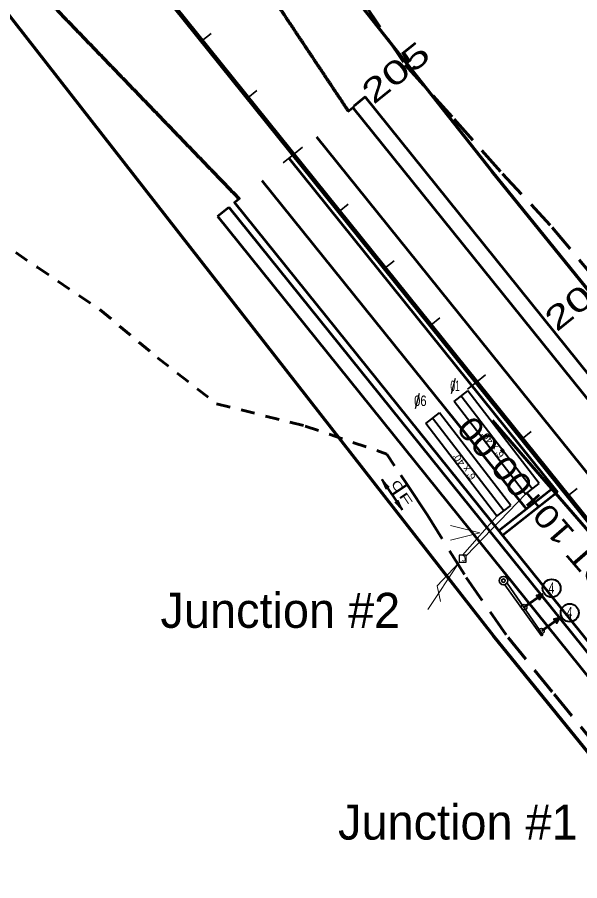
# Model space of a CAD drawing. Extents: x 2717836 to 2719883, y 337327 to 339813.
# Drawn here: x 2718118.9 to 2718311.5, y 339092.2 to 339388.1 of the extents above; entities that cross this region are included whole.
import ezdxf
from ezdxf.enums import TextEntityAlignment as Align

# ---------------------------------------------------------------- set-up
doc = ezdxf.new("R2010")
doc.units = 0
doc.header["$LTSCALE"] = 3.2
for name, pattern in [('LONG_DASHED', [7.5, 6, -1.5]), ('MEDIUM_DASHED', [4.5, 3, -1.5]), ('SHORT_DASHED', [2.7, 1.5, -1.2])]:
    doc.linetypes.add(name, pattern=pattern)
for name, color, linetype, lineweight in [('1', 7, 'Continuous', 106), ('17', 7, 'Continuous', 40), ('18', 7, 'Continuous', 35), ('2', 7, 'Continuous', 13), ('22', 7, 'SHORT_DASHED', 60), ('23', 7, 'Continuous', 70), ('28', 7, 'Continuous', 25), ('3', 7, 'Continuous', 70), ('31', 7, 'Continuous', 35), ('4', 7, 'Continuous', 53), ('50', 7, 'Continuous', 13), ('52', 7, 'Continuous', 53), ('7', 7, 'Continuous', 53)]:
    doc.layers.add(name, color=color, linetype=linetype, lineweight=lineweight)

msp = doc.modelspace()

# ---------------------------------------------------------------- hatches: boundary and pattern name
at = {"layer": '52'}
for points in [[(2718243.745, 339229.709), (2718246.246, 339227.048), (2718245.241, 339227.459), (2718245.221, 339226.365)], [(2718250.677, 339219.307), (2718248.176, 339221.969), (2718249.182, 339221.558), (2718249.201, 339222.652)]]:
    msp.add_hatch(color=256, dxfattribs=at).paths.add_polyline_path(points)

# ---------------------------------------------------------------- linework, layer by layer
at = {"layer": '1'}
msp.add_line((2717900.042, 339730.601), (2718401.027, 339107.905), dxfattribs=at)
at = {"layer": '1', "lineweight": 13}
msp.add_lwpolyline([(2718267.269, 339213.9), (2718277.269, 339211.4), (2718267.269, 339208.9)], dxfattribs=at)
at = {"layer": '17'}
for p, q in [((2718268.483, 339256.414), (2718273.236, 339260.076)), ((2718295.271, 339226.558), (2718270.859, 339258.245)), ((2718297.648, 339228.389), (2718273.236, 339260.076)), ((2718292.895, 339224.727), (2718268.483, 339256.414)), ((2718258.76, 339248.883), (2718263.513, 339252.545)), ((2718287.925, 339220.858), (2718263.513, 339252.545)), ((2718283.172, 339217.196), (2718258.76, 339248.883)), ((2718285.548, 339219.027), (2718261.136, 339250.714)), ((2718292.895, 339224.727), (2718297.648, 339228.389)), ((2718283.172, 339217.196), (2718287.925, 339220.858))]:
    msp.add_line(p, q, dxfattribs=at)
at = {"layer": '17', "lineweight": 25}
msp.add_lwpolyline([(2718270.265, 339203.803), (2718270.265, 339201.403), (2718272.665, 339201.403), (2718272.665, 339203.803)], close=True, dxfattribs=at)
at = {"layer": '18'}
for p, q in [((2718286.407, 339197.797), (2718286.44, 339197.796)), ((2718298.438, 339176.096), (2718285.836, 339193.638))]:
    msp.add_line(p, q, dxfattribs=at)
at = {"layer": '18', "lineweight": 60}
for p, q in [((2718298.846, 339190.415), (2718292.565, 339186.048)), ((2718304.717, 339182.352), (2718298.514, 339177.874))]:
    msp.add_line(p, q, dxfattribs=at)
at = {"layer": '18'}
msp.add_lwpolyline([(2718286.613, 339194.252), (2718298.867, 339176.528), (2718298.438, 339176.096)], dxfattribs=at)
at = {"layer": '18', "lineweight": 40}
for points in [[(2718298.846, 339190.415), (2718296.75, 339190.002), (2718297.729, 339188.594)], [(2718304.717, 339182.352), (2718302.629, 339181.902), (2718303.632, 339180.512)]]:
    msp.add_lwpolyline(points, close=True, dxfattribs=at)
at = {"layer": '18'}
for radius in [1.448, 0.621]:
    msp.add_circle((2718285.395, 339195.059), radius, dxfattribs=at)
at = {"layer": '18', "lineweight": 40}
for centre in [(2718301.9, 339192.442), (2718308.096, 339184.054)]:
    msp.add_circle(centre, 3.09, dxfattribs=at)
at = {"layer": '18', "lineweight": 25}
for centre in [(2718292.485, 339185.989), (2718298.435, 339177.814)]:
    msp.add_circle(centre, 0.96, dxfattribs=at)
at = {"layer": '2', "lineweight": 53}
for p, q in [((2718302.51, 339226.85), (2718283.843, 339212.08)), ((2718303.918, 339225.414), (2718285.097, 339210.521))]:
    msp.add_line(p, q, dxfattribs=at)
at = {"layer": '2'}
msp.add_lwpolyline([(2718259.544, 339185.135), (2718270.069, 339201.126), (2718262.662, 339193.326), (2718263.832, 339187.865)], dxfattribs=at)
at = {"layer": '22', "linetype": 'MEDIUM_DASHED'}
for p, q in [((2718237.804, 339392.698), (2718251.724, 339371.81)), ((2718251.724, 339371.81), (2718268.485, 339353.209)), ((2718268.485, 339353.209), (2718285.099, 339334.488)), ((2718285.099, 339334.488), (2718302.106, 339316.085)), ((2718302.106, 339316.085), (2718318.127, 339296.888)), ((2718259.373, 339217.531), (2718272.661, 339196.135)), ((2718272.661, 339196.135), (2718286.987, 339175.575)), ((2718286.987, 339175.575), (2718302.767, 339156.183)), ((2718302.767, 339156.183), (2718318.581, 339136.82))]:
    msp.add_line(p, q, dxfattribs=at)
at = {"layer": '22'}
for p, q in [((2718104.052, 339317.175), (2718125.672, 339302.483)), ((2718125.672, 339302.483), (2718147.311, 339287.806)), ((2718147.311, 339287.806), (2718166.862, 339271.448)), ((2718166.862, 339271.448), (2718187.132, 339255.67)), ((2718187.132, 339255.67), (2718217.512, 339248.025)), ((2718217.512, 339248.025), (2718245.459, 339238.423)), ((2718245.459, 339238.423), (2718252.416, 339227.977))]:
    msp.add_line(p, q, dxfattribs=at)
at = {"layer": '22', "linetype": 'LONG_DASHED'}
msp.add_line((2718252.416, 339227.977), (2718259.373, 339217.531), dxfattribs=at)
at = {"layer": '23'}
for p, q in [((2718281.942, 339176.113), (2718019.958, 339512.184)), ((2718281.562, 339335.271), (2718222.313, 339410.323))]:
    msp.add_line(p, q, dxfattribs=at)
for points in [[(2718450.804, 339126.177), (2718423.202, 339160.278), (2718356.64, 339242.515), (2718281.562, 339335.271)], [(2718625.836, 338603.023), (2718449.262, 338959.135), (2718424.429, 339000.578), (2718281.942, 339176.113)]]:
    msp.add_lwpolyline(points, dxfattribs=at)
at = {"layer": '28'}
for p, q in [((2718267.641, 339259.176), (2718269.003, 339264.412)), ((2718255.249, 339254.07), (2718256.612, 339259.306))]:
    msp.add_line(p, q, dxfattribs=at)
at = {"layer": '3'}
for points in [[(2718125.07, 339398.259), (2718125.544, 339397.767), (2718126.011, 339397.283), (2718126.485, 339396.792), (2718126.952, 339396.308), (2718127.426, 339395.816), (2718127.893, 339395.332), (2718128.367, 339394.84), (2718128.841, 339394.349), (2718129.308, 339393.865), (2718129.782, 339393.373), (2718130.249, 339392.889), (2718130.723, 339392.398), (2718131.19, 339391.914), (2718131.664, 339391.422), (2718132.137, 339390.93), (2718132.605, 339390.446), (2718133.078, 339389.955), (2718133.546, 339389.471), (2718134.019, 339388.979), (2718134.487, 339388.495), (2718134.96, 339388.003), (2718135.428, 339387.52), (2718135.901, 339387.028), (2718136.375, 339386.536), (2718136.842, 339386.052), (2718137.316, 339385.561), (2718137.783, 339385.077), (2718138.257, 339384.585), (2718138.724, 339384.101), (2718139.198, 339383.609), (2718139.672, 339383.118), (2718140.139, 339382.634), (2718140.613, 339382.142), (2718141.08, 339381.658), (2718141.554, 339381.166), (2718142.021, 339380.683), (2718142.495, 339380.191), (2718142.968, 339379.699), (2718143.436, 339379.215), (2718143.909, 339378.724), (2718144.377, 339378.24), (2718144.85, 339377.748), (2718145.318, 339377.264), (2718145.791, 339376.772), (2718146.265, 339376.281), (2718146.732, 339375.797), (2718147.206, 339375.305), (2718147.673, 339374.821), (2718148.147, 339374.329), (2718148.614, 339373.846), (2718149.088, 339373.354), (2718149.562, 339372.862), (2718150.029, 339372.378), (2718150.503, 339371.887), (2718150.97, 339371.403), (2718151.444, 339370.911), (2718151.911, 339370.427), (2718152.385, 339369.935), (2718152.852, 339369.451), (2718153.326, 339368.96), (2718153.799, 339368.468), (2718154.267, 339367.984), (2718154.74, 339367.492), (2718155.208, 339367.009), (2718155.681, 339366.517), (2718156.149, 339366.033), (2718156.622, 339365.541), (2718157.096, 339365.05), (2718157.563, 339364.566), (2718158.037, 339364.074), (2718158.504, 339363.59), (2718158.978, 339363.098), (2718159.445, 339362.614), (2718159.919, 339362.123)], [(2718204.33, 339397.853), (2718204.709, 339397.285), (2718205.081, 339396.725), (2718205.46, 339396.157), (2718205.833, 339395.597), (2718206.212, 339395.029), (2718206.584, 339394.469), (2718206.963, 339393.901), (2718207.342, 339393.333), (2718207.715, 339392.773), (2718208.094, 339392.205), (2718208.466, 339391.645), (2718208.845, 339391.077), (2718209.218, 339390.517), (2718209.597, 339389.949), (2718209.975, 339389.381), (2718210.348, 339388.821), (2718210.727, 339388.253), (2718211.1, 339387.693), (2718211.478, 339387.125), (2718211.851, 339386.565), (2718212.23, 339385.997), (2718212.603, 339385.437), (2718212.981, 339384.869), (2718213.36, 339384.301), (2718213.733, 339383.741), (2718214.112, 339383.173), (2718214.484, 339382.612), (2718214.863, 339382.044), (2718215.236, 339381.484), (2718215.615, 339380.916), (2718215.994, 339380.348), (2718216.366, 339379.788), (2718216.745, 339379.22), (2718217.118, 339378.66), (2718217.497, 339378.092), (2718217.869, 339377.532), (2718218.248, 339376.964), (2718218.627, 339376.396), (2718219, 339375.836), (2718219.378, 339375.268), (2718219.751, 339374.708), (2718220.13, 339374.14), (2718220.503, 339373.58), (2718220.881, 339373.012), (2718221.26, 339372.444), (2718221.633, 339371.884), (2718222.012, 339371.316), (2718222.384, 339370.756), (2718222.763, 339370.188), (2718223.136, 339369.628), (2718223.515, 339369.06), (2718223.894, 339368.492), (2718224.266, 339367.932), (2718224.645, 339367.364), (2718225.018, 339366.804), (2718225.397, 339366.236), (2718225.769, 339365.676), (2718226.148, 339365.108), (2718226.521, 339364.548), (2718226.9, 339363.98), (2718227.278, 339363.412), (2718227.651, 339362.852), (2718228.03, 339362.284), (2718228.403, 339361.724), (2718228.781, 339361.156), (2718229.154, 339360.595), (2718229.533, 339360.028), (2718229.912, 339359.46), (2718230.284, 339358.899), (2718230.663, 339358.331), (2718231.036, 339357.771), (2718231.415, 339357.203), (2718232.166, 339356.075)], [(2718159.919, 339362.123), (2718160.393, 339361.631), (2718160.86, 339361.147), (2718161.334, 339360.655), (2718161.801, 339360.172), (2718162.275, 339359.68), (2718162.742, 339359.196), (2718163.216, 339358.704), (2718163.689, 339358.213), (2718164.157, 339357.729), (2718164.63, 339357.237), (2718165.098, 339356.753), (2718165.571, 339356.261), (2718166.039, 339355.777), (2718166.512, 339355.286), (2718166.986, 339354.794), (2718167.453, 339354.31), (2718167.927, 339353.818), (2718168.394, 339353.335), (2718168.868, 339352.843), (2718169.335, 339352.359), (2718169.809, 339351.867), (2718170.276, 339351.383), (2718170.75, 339350.892), (2718171.224, 339350.4), (2718171.691, 339349.916), (2718172.165, 339349.424), (2718172.632, 339348.94), (2718173.106, 339348.449), (2718173.573, 339347.965), (2718174.047, 339347.473), (2718174.52, 339346.981), (2718174.988, 339346.498), (2718175.461, 339346.006), (2718175.929, 339345.522), (2718176.402, 339345.03), (2718176.87, 339344.546), (2718177.343, 339344.055), (2718177.817, 339343.563), (2718178.284, 339343.079), (2718178.758, 339342.587), (2718179.225, 339342.103), (2718179.699, 339341.612), (2718180.166, 339341.128), (2718180.64, 339340.636), (2718181.114, 339340.144), (2718181.581, 339339.661), (2718182.055, 339339.169), (2718182.522, 339338.685), (2718182.996, 339338.193), (2718183.463, 339337.709), (2718183.937, 339337.218), (2718184.41, 339336.726), (2718184.878, 339336.242), (2718185.351, 339335.75), (2718185.819, 339335.266), (2718186.292, 339334.775), (2718186.76, 339334.291), (2718187.233, 339333.799), (2718187.701, 339333.315), (2718188.174, 339332.824), (2718188.648, 339332.332), (2718189.115, 339331.848), (2718189.589, 339331.356), (2718190.056, 339330.872), (2718190.53, 339330.381), (2718190.997, 339329.897), (2718191.471, 339329.405), (2718191.945, 339328.913), (2718192.412, 339328.429), (2718192.886, 339327.938), (2718193.353, 339327.454), (2718193.827, 339326.962), (2718194.768, 339325.987)]]:
    msp.add_spline(points, degree=3, dxfattribs=at)
at = {"layer": '31'}
for p, q in [((2718182.124, 339379.988), (2718185.241, 339382.495)), ((2718197.796, 339360.509), (2718200.912, 339363.017)), ((2718213.467, 339341.031), (2718216.583, 339343.538)), ((2718213.467, 339341.031), (2718209.976, 339338.223)), ((2718229.138, 339321.552), (2718232.255, 339324.06)), ((2718244.809, 339302.074), (2718247.926, 339304.581)), ((2718260.481, 339282.595), (2718263.597, 339285.103)), ((2718276.152, 339263.117), (2718279.268, 339265.624)), ((2718276.152, 339263.117), (2718273.035, 339260.61)), ((2718291.823, 339243.638), (2718294.94, 339246.146)), ((2718307.494, 339224.16), (2718310.611, 339226.667))]:
    msp.add_line(p, q, dxfattribs=at)
at = {"layer": '31', "lineweight": 60}
msp.add_line((2718352.184, 339168.496), (2718281.617, 339249.878), dxfattribs=at)
at = {"layer": '4'}
for p, q in [((2718232.117, 339355.818), (2718234.221, 339357.51)), ((2718323.984, 339245.141), (2718233.831, 339357.196)), ((2718221.365, 339347.167), (2718315.812, 339229.774)), ((2718212.015, 339339.645), (2718303.918, 339225.414)), ((2718202.666, 339332.122), (2718293.254, 339219.526)), ((2718195.164, 339326.088), (2718193.061, 339324.395)), ((2718193.316, 339324.6), (2718380.769, 339091.606))]:
    msp.add_line(p, q, dxfattribs=at)
at = {"layer": '50'}
for p, q in [((2718272.626, 339203.514), (2718292.895, 339224.727)), ((2718271.427, 339203.834), (2718283.172, 339217.196))]:
    msp.add_line(p, q, dxfattribs=at)
at = {"layer": '52'}
for p, q in [((2718243.745, 339229.709), (2718250.677, 339219.307)), ((2718247.211, 339224.508), (2718252.416, 339227.977))]:
    msp.add_line(p, q, dxfattribs=at)
at = {"layer": '52', "lineweight": 25}
for points in [[(2718243.745, 339229.709), (2718246.246, 339227.048), (2718245.241, 339227.459), (2718245.221, 339226.365)], [(2718250.677, 339219.307), (2718248.176, 339221.969), (2718249.182, 339221.558), (2718249.201, 339222.652)]]:
    msp.add_lwpolyline(points, close=True, dxfattribs=at)
at = {"layer": '7'}
for p, q in [((2718238.01, 339360.777), (2718234.114, 339357.642)), ((2718328.27, 339248.589), (2718238.01, 339360.777)), ((2718187.473, 339319.899), (2718191.368, 339323.033)), ((2718191.368, 339323.033), (2718378.821, 339090.039)), ((2718187.473, 339319.899), (2718374.925, 339086.905))]:
    msp.add_line(p, q, dxfattribs=at)

# ---------------------------------------------------------------- texts
at = {"layer": '17'}
for s, height, rotation, width, p in [("6' x 40'", 2.4, 127.611, 1.05, (2718282.656, 339242.361)), ("6' x 40'", 2.4, 127.611, 1.05, (2718272.933, 339234.83)), ('J', 1.92, 12.014, 1.15, (2718272, 339201.73))]:
    msp.add_text(s, height=height, rotation=rotation, dxfattribs=dict(at, width=width)).set_placement(p, align=Align.CENTER)
at = {"layer": '18', "width": 0.7}
for p in [(2718300.753, 339190.637), (2718306.949, 339182.25)]:
    msp.add_text('4', height=3.84, rotation=358.176, dxfattribs=at).set_placement(p)
at = {"layer": '2'}
for s, p in [('Junction #2', (2718167.94, 339178.887)), ('Junction #1', (2718228.75, 339106.345))]:
    msp.add_text(s, height=12, dxfattribs=at).set_placement(p)
at = {"layer": '28'}
for s, width, p in [('01', 0.6, (2718268.823, 339259.993)), ('06', 0.8, (2718256.927, 339254.887))]:
    msp.add_text(s, height=3.6, rotation=359.906, dxfattribs=dict(at, width=width)).set_placement(p, align=Align.CENTER)
at = {"layer": '31'}
for s, rotation, width, p in [('205', 38.818, 1.45, (2718240.907, 339357.974)), ('206', 38.818, 1.45, (2718303.592, 339280.06)), ('POT 10+00.00', 130.929, 1.2, (2718329.886, 339188.869))]:
    msp.add_text(s, height=8, rotation=rotation, dxfattribs=dict(at, width=width)).set_placement(p)
at = {"layer": '52'}
for s, width, p in [('C', 1.4, (2718247.875, 339226.641)), ('F', 1.9, (2718250.696, 339222.203))]:
    msp.add_text(s, height=3, rotation=303.684, dxfattribs=dict(at, width=width)).set_placement(p, align=Align.CENTER)

doc.saveas('drawing.dxf')
